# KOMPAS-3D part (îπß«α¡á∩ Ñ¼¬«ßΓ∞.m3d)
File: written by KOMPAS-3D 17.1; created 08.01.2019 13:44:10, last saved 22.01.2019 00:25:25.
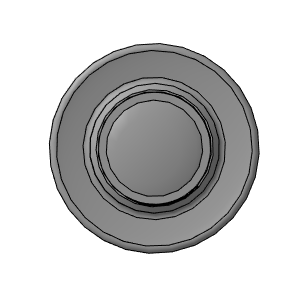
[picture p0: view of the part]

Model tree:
1. Эскиз:1
2. Операция вращения:1
     Угол 1 = 360
3. Эскиз:5
4. Спираль цилиндрическая:2
     Число витков = 2; Шаг = 2.5; Высота = 5; Диаметр 1 = 40.3; Диаметр 2 = 10
5. Эскиз:6
6. Вырезать кинематический элемент:2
